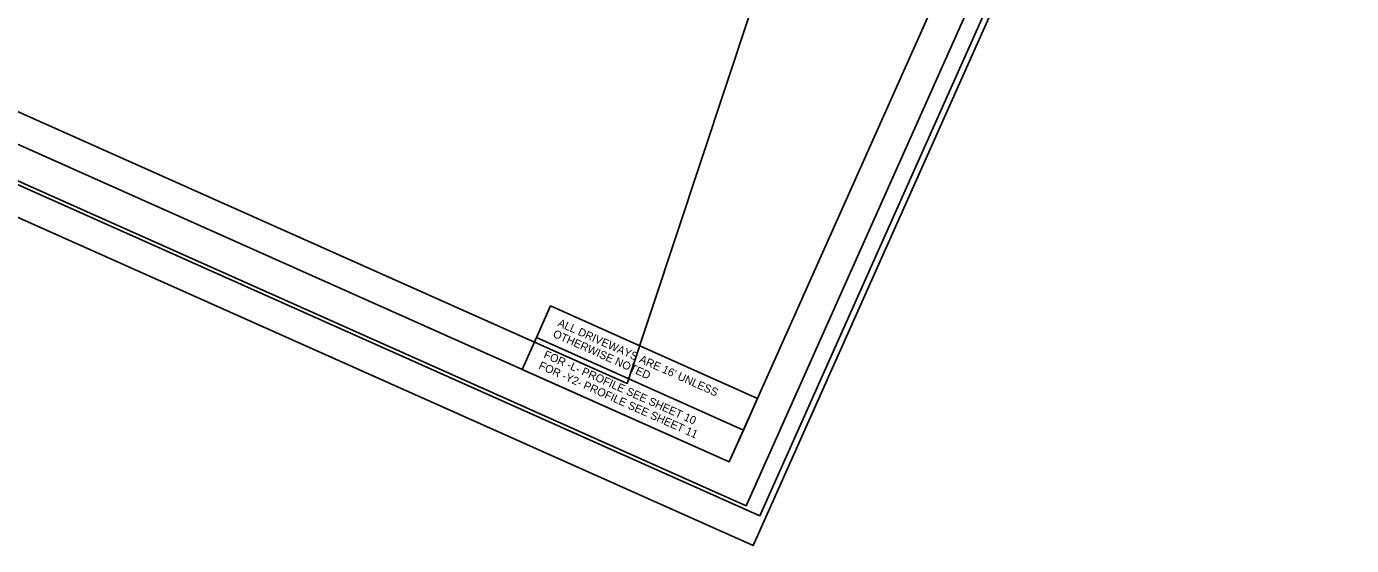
# Model space of a CAD drawing. Extents: x 2297991 to 2299183, y 599186 to 600200.
# Drawn here: x 2298587 to 2299183, y 599186 to 599419 of the extents above; entities that cross this region are included whole.
import ezdxf

# ---------------------------------------------------------------- set-up
doc = ezdxf.new("R2010")
doc.units = 0
for name, color, linetype in [('Exist DTM Drainline Cogo Comment', 7, 'Continuous'), ('Exist DTM Drainline Cogo Elevation', 7, 'Continuous'), ('Exist DTM Drainline Cogo Number', 7, 'Continuous'), ('Exist DTM Drainline Cogo Point CELL', 7, 'Continuous'), ('Exist Property Iron Pin Cogo Number', 7, 'Continuous'), ('Exist Roads EOP Cogo Comment', 7, 'Continuous'), ('Exist Roads EOP Cogo Elevation', 7, 'Continuous'), ('Exist Roads EOP Cogo Number', 7, 'Continuous')]:
    doc.layers.add(name, color=color, linetype=linetype)

msp = doc.modelspace()

# ---------------------------------------------------------------- linework, layer by layer
at = {"layer": 'Exist DTM Drainline Cogo Comment'}
msp.add_lwpolyline([(2298345.56, 600145.92), (2298088.78, 599570.64), (2298910.61, 599203.78), (2299118.52, 599669.59), (2299008.92, 599718.52), (2299057.79, 599827.99)], close=True, dxfattribs=at)
at = {"layer": 'Exist DTM Drainline Cogo Elevation'}
msp.add_lwpolyline([(2299182.82, 599788.6), (2298260.17, 600200.46), (2297991.14, 599597.77), (2298913.79, 599185.92)], close=True, dxfattribs=at)
at = {"layer": 'Exist DTM Drainline Cogo Number'}
msp.add_lwpolyline([(2299174.87, 599777.4), (2298261.8, 600184.98), (2298003.76, 599606.9), (2298916.82, 599199.32)], close=True, dxfattribs=at)
at = {"layer": 'Exist DTM Drainline Cogo Point CELL'}
msp.add_lwpolyline([(2299167.39, 599779.06), (2298345.56, 600145.92), (2298088.76, 599570.63), (2298910.59, 599203.77)], close=True, dxfattribs=at)
at = {"layer": 'Exist Property Iron Pin Cogo Number'}
msp.add_lwpolyline([(2298166.71, 599708.44), (2298114.07, 599590.51), (2298857.04, 599258.86), (2299012.14, 599726.11), (2298998.59, 599732.16), (2299037.98, 599820.4), (2298552.35, 600037.18)], close=True, dxfattribs=at)
at = {"layer": 'Exist Roads EOP Cogo Comment'}
msp.add_lwpolyline([(2298353.14, 600126.1), (2298108.59, 599578.22), (2298903.03, 599223.59), (2299108.19, 599683.24), (2298998.59, 599732.16), (2299037.98, 599820.4)], close=True, dxfattribs=at)
at = {"layer": 'Exist Roads EOP Cogo Number'}
for points in [[(2298816.28, 599279.41), (2298909.39, 599237.84), (2298915.75, 599252.1), (2298822.64, 599293.66)], [(2298809.92, 599265.16), (2298903.03, 599223.59), (2298909.39, 599237.84), (2298816.28, 599279.41)]]:
    msp.add_lwpolyline(points, close=True, dxfattribs=at)

# ---------------------------------------------------------------- texts
at = {"layer": 'Exist Roads EOP Cogo Elevation'}
for s, p in [('OTHERWISE NOTED', (2298823.37, 599279.86)), ("ALL DRIVEWAYS ARE 16' UNLESS ", (2298825.57, 599284.79)), ('FOR -L- PROFILE SEE SHEET 10', (2298819.21, 599270.54)), ('FOR -Y2- PROFILE SEE SHEET 11', (2298817.01, 599265.61))]:
    msp.add_text(s, height=3.6, rotation=335.94476, dxfattribs=at).set_placement(p)

doc.saveas('drawing.dxf')
